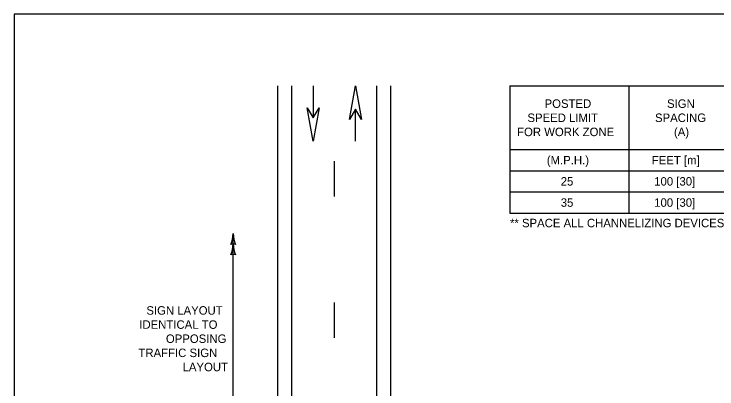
# Model space of a CAD drawing. Extents: x 49991.4 to 50021, y 49987.6 to 50011.4.
# Drawn here: x 50000.336 to 50005.306, y 50008.61 to 50011.263 of the extents above; entities that cross this region are included whole.
import ezdxf

# ---------------------------------------------------------------- set-up
doc = ezdxf.new("R2010")
doc.units = 0
for name, color, linetype in [('Level 1', 7, 'Continuous'), ('Level 2', 7, 'Continuous'), ('Level 3', 7, 'Continuous')]:
    doc.layers.add(name, color=color, linetype=linetype)

msp = doc.modelspace()

# ---------------------------------------------------------------- linework, layer by layer
at = {"layer": 'Level 1'}
for p, q in [((50002.201, 50000.5714), (50002.201, 50010.7538)), ((50002.301, 50000.5714), (50002.301, 50010.7538)), ((50002.4509, 50010.7538), (50002.4509, 50010.5279)), ((50002.4512, 50010.7538), (50002.4512, 50010.5279)), ((50002.901, 50005.8214), (50002.901, 50010.7538)), ((50003.001, 50000.5714), (50003.001, 50010.7538)), ((50002.7506, 50010.3637), (50002.7506, 50010.5896)), ((50002.7509, 50010.3637), (50002.7509, 50010.5896)), ((50002.601, 50009.9716), (50002.601, 50010.2216)), ((50002.601, 50008.9716), (50002.601, 50009.2216))]:
    msp.add_line(p, q, dxfattribs=at)
for points in [[(50008.6146, 50011.2628), (50000.3356, 50011.2628), (50000.3356, 50000.0624), (50008.6146, 50000.0624)], [(50002.7089, 50010.5173), (50002.7506, 50010.7538), (50002.7925, 50010.5173), (50002.7506, 50010.5895)], [(50002.4929, 50010.6002), (50002.4512, 50010.3637), (50002.4093, 50010.6002), (50002.4512, 50010.528)]]:
    msp.add_lwpolyline(points, close=True, dxfattribs=at)
at = {"layer": 'Level 2'}
for p, q in [((50003.8428, 50010.7538), (50007.7728, 50010.7538)), ((50003.8428, 50010.7538), (50003.8428, 50009.8538)), ((50004.6828, 50010.7538), (50004.6828, 50009.8538)), ((50003.8428, 50010.3038), (50007.7728, 50010.3038)), ((50003.8428, 50010.1538), (50007.7728, 50010.1538)), ((50003.8428, 50010.0038), (50007.7728, 50010.0038)), ((50003.8428, 50009.8538), (50007.7728, 50009.8538))]:
    msp.add_line(p, q, dxfattribs=at)
at = {"layer": 'Level 3'}
msp.add_line((50001.885, 50008.2214), (50001.885, 50009.709), dxfattribs=at)
for centre, radius, start, end in [((50001.6523, 50009.7205), 0.233, 337.9228, 357.1727), ((50002.1071, 50009.7181), 0.2223, 182.3605, 202.544), ((50001.885, 50009.5807), 0.0548, 72.1388, 107.8612), ((50001.6523, 50009.647), 0.233, 337.9228, 357.1727), ((50002.1071, 50009.6447), 0.2223, 182.3605, 202.544), ((50001.885, 50009.5073), 0.0548, 72.1388, 107.8612)]:
    msp.add_arc(centre, radius, start, end, dxfattribs=at)

# ---------------------------------------------------------------- texts
at = {"layer": 'Level 2'}
for s, p in [('POSTED', (50004.0875, 50010.5988)), ('SIGN', (50004.9534, 50010.5988)), ('SPEED LIMIT', (50003.9662, 50010.4988)), ('SPACING', (50004.8684, 50010.4988)), ('FOR WORK ZONE', (50003.8932, 50010.3988)), ('(A)', (50005.0025, 50010.3988)), ('(M.P.H.)', (50004.1031, 50010.1988)), ('FEET [m]', (50004.8455, 50010.1988)), ('25', (50004.2016, 50010.0488)), ('100 [30]', (50004.8627, 50010.0488)), ('35', (50004.2017, 50009.8988)), ('100 [30]', (50004.8627, 50009.8988)), ('** SPACE ALL CHANNELIZING DEVICES AT "G" UNLESS OTHERWISE NOTED.', (50003.8428, 50009.7538)), ('SIGN LAYOUT', (50001.2715, 50009.1352)), ('IDENTICAL TO', (50001.2213, 50009.0352)), ('OPPOSING', (50001.4094, 50008.9352)), ('TRAFFIC SIGN', (50001.2154, 50008.8352)), ('LAYOUT', (50001.5275, 50008.7352))]:
    msp.add_text(s, height=0.06, dxfattribs=at).set_placement(p)

doc.saveas('drawing.dxf')
